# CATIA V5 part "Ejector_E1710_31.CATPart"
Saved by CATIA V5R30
Part number: Vyhazovac_7x160_7
Nomenclature: E1710/7x160
Description: MEUSBURGER
Property "Material": "1.221"
Publications: "__DrillHole", "Base"
Bounding box of the stored display mesh (mm): x -5.992 to 5.992, y -5.992 to 5.992, z 0 to 151
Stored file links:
  E:\Bakalarka\Model\Forma_v7\Ejector_E1710_31.CATPart
  E:\dev\MoldDesign\intel_a\startup\components\MoldCatalog\Ejector\Meusburger\Ejector_E1710\TableE1710.txt
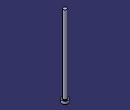
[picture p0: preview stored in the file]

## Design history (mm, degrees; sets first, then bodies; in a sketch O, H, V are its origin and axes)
Parameters
  Ref = "E1710/7x160" {design table}
  D1 = 7 mm {design table}
  D3 = 12 mm {design table}
  L = 160 mm {design table}
  L3 = 5 mm {design table}
  R = 0.5 mm {design table}
  k_d3 = 13 mm {design table}
  k_d1 = 7.2 mm {design table}
  k_F = 0.5 mm {design table}
  kl = 17 mm {design table}
  Mat = "1.221" {design table}
  HeatTreat = "ISO6751" {design table}
  Offset_Parting = 10 mm
  Anti_Rotation = "Normal"
  Anti_Rotation_D = 4 mm
  Anti_Rotation_D_Icut = 4 mm
  Add_Length_L = 1.3377 mm
  Add_Length_D3 = 0 mm
  SupplierRef = "Meusburger 2017"
  BmpRef = "F_MldEjectorD1"
  DrillHole_Length = 225 mm
  ValidationTest = false
  Anti_Rotation_D_min = 4 mm {= OffSet_D1 /2}
  Anti_Rotation_D_max = 5.925 mm {= D3/2-0.075mm}
  Anti_Rotation_D_ref = 4 mm {= Anti_Rotation_D}
  Anti_Rotation_D_Icut_ref = 4 mm {= Anti_Rotation_D_Icut}
  Anti_Rotation_Ref_Icut = 2.3246 mm
  Offset_L = 20 mm
  D = 7 mm {= D1}
  OffSet_D1 = 8 mm {= D1+2*R}
  OffSet_D3 = 13 mm {= D3+1mm}
  XG_Split = 54.5 mm
  YG_Split = -4 mm
  ZG_Split = -198 mm
  DirX_Split = 0 mm
  DirY_Split = 0 mm
  DirZ_Split = 1 mm
Set1 "BaseBody"
  Point1 "Base": (0, 0, 0)
  Plane1: type Offset, RefPlane xy-plane, Offset 225 {= DrillHole_Length}, reversed
  Sketch1 "Sketch.2" on xy-plane, origin (0, 0, 0), H (1, 0, 0), V (0, 1, 0)
    point P1 (-0.46, 1.1623)
    point P2 (0.46, 1.1623)
    construction line L1 (-0.46, 1.1623) -> (0.46, 1.1623)
    point P3 (0.46, -1.1623)
    line L2 (0.46, -1.1623) -> (0.46, 1.1623)
    point P4 (-0.46, -1.1623)
    construction line L3 (0.46, -1.1623) -> (-0.46, -1.1623)
    line L4 (-0.46, 1.1623) -> (-0.46, -1.1623)
    point P5 (-0.21, 1.1623)
    arc A1 centre (-0.21, 1.1623) radius 0.25 from (-0.21, 1.4123) to (-0.46, 1.1623) ccw
    point P7 (0.21, 1.1623)
    point P8 (0.21, 1.4123)
    arc A2 centre (0.21, 1.1623) radius 0.25 from (0.46, 1.1623) to (0.21, 1.4123) ccw
    line L5 (-0.21, 1.4123) -> (0.21, 1.4123)
    point P9 (-0.46, -1.1623)
    arc A3 centre (-0.21, -1.1623) radius 0.25 from (-0.46, -1.1623) to (-0.21, -1.4123) ccw
    point P11 (0.21, -1.4123)
    line L6 (-0.21, -1.4123) -> (0.21, -1.4123)
    point P12 (0.46, -1.1623)
    arc A4 centre (0.21, -1.1623) radius 0.25 from (0.21, -1.4123) to (0.46, -1.1623) ccw
    point P14 (-0.46, 1.1623)
    point P15 (-0.46, -1.1623)
    point P16 (0.46, 1.1623)
    point P17 (0.46, -1.1623)
    reference projected circle E1 centre (0, 0) radius 1.25 from edge [face of Shaft1 from Sketch2.L3 | face of Shaft1 from Sketch2.L4]
    reference projected circle E2 centre (0, 0) radius 1.25 from edge [face of Shaft1 from Sketch2.L3 | face of Shaft1 from Sketch2.L4]
    reference projected circle E3 centre (0, 0) radius 1.25 from edge [face of Shaft1 from Sketch2.L3 | face of Shaft1 from Sketch2.L4]
    reference projected circle E4 centre (0, 0) radius 1.25 from edge [face of Shaft1 from Sketch2.L3 | face of Shaft1 from Sketch2.L4]
    point P18 (-0.46, -1.1623)
    point P19 (-0.21, -1.4123)
    point P20 (0.21, -1.4123)
    point P21 (0.46, -1.1623)
    point P22 (-0.21, -1.4123)
    point P23 (0.21, -1.4123)
    distance P14 P15 = 2.3246 (reference)
    distance P16 P17 = 2.3246 (reference)
    distance L1 P14 = 0 (reference)
    radius A1 = 3.5
    distance L4 V = 4.01
    distance L2 V = 5.935
    distance L5 L6 = 12
    horizontal: L1 H, L3 H, L5 H
    vertical: L2 V, L4 V
    coincidence: P5 L1, P7 L1, P3 P12, P14 L4, P15 L4, P16 L2, P17 L2, P14 E1, P15 E2, P16 E3, P17 E4, P3 P21, P4 P18, P20 P23, P19 P22
    tangency: A1 L4, A2 L2, A2 L5, A1 L5
    symmetry: P1 P9 H, A1 A3 H, P8 P11 H, L5 L6 H, P2 P12 H, A2 A4 H
  DatumSurface1
Body1 "PartBody" (main body)
  Sketch2 "Sketch.1" on zx-plane, origin (0, 0, 0), H (-1, 0, 0), V (0, 0, 1)
    point P1 (0, 160)
    line L1 (3.5, 160) -> (0, 160)
    line L2 (3.5, 5) -> (3.5, 160)
    line L3 (6, 5) -> (3.5, 5)
    line L4 (6, 0) -> (6, 5)
    point P5 (0, 0)
    line L5 (0, 0) -> (6, 0)
    point P6 (0, 160)
    axis line L6 (0, 160) -> (0, 0)
    point P7 (0, 0)
    point P8 (3.5, 5)
    point P9 (3.5, 5)
    line L7 (0, 160) -> (0, 0)
    distance L5 L3 = 5 {= L3}
    distance L5 L1 = 160 {= L}
    distance L2 L6 = 3.5 {= D1 /2}
    distance L4 L6 = 6 {= D3 /2}
    coincidence: L6 P5, P1 L6, L5 H, L6 V, P7 O, P6 P1, P8 P9
    vertical: L2 V, L7 V
    horizontal: L1 H
  Shaft1 "Shaft.1": profile Sketch2, axis Sketch2.L6, angle 360
  Pocket1 "Pocket.1": profile Sketch1, direction (0, 0, 1), length 6, outer side, deactivated
  Pocket2 "Pocket.2": profile Sketch1, direction (0, 0, 1), length 6, outer side, deactivated
  Fillet1: radius 0.5 {= R}, on edge [face of Shaft1 from Sketch2.L2 | face of Shaft1 from Sketch2.L3]
  Pocket3: profile face of Shaft1 from Sketch2.L1, direction along face of Shaft1 from Sketch2.L1, length 225
  Pocket4: profile face of Pocket3, direction along face of Pocket3 reversed, up to face of DatumSurface1
Body2 "__DrillHole"
  Sketch3 "Sketch.3" on face of Shaft1, origin (0, 0, 0), H (1, 0, 0), V (0, -1, 0)
    point P1 (0, 0)
    reference projected point E1 (0, 0) from Point1
    coincidence: E1 P1
  Hole1 "Hole.1": placed by Sketch3, at (0, 0, 0) direction (0, 0, 1), diameter 8 {= OffSet_D1}, depth 140 {= L-Offset_L}
  Sketch4 "Sketch.4" on face of Shaft1, origin (0, 0, 0), H (1, 0, 0), V (0, -1, 0)
    point P1 (0, 0)
    reference projected point E1 (0, 0) from Point1
    coincidence: E1 P1
  Hole2 "Hole.2": placed by Sketch4, at (0, 0, 0) direction (0, 0, 1), diameter 7 {= D1}, depth 160 {= L}
  Sketch5 "Sketch.5" on face of Shaft1 from Sketch2.L3, origin (0, 0, 5), H (1, 0, 0), V (0, 1, 0)
    point P1 (0, 0)
    reference projected point E1 (0, 0) from Point1
    coincidence: E1 P1
  Hole3 "Hole.3": placed by Sketch5, at (0, 0, 5) direction (0, 0, -1), diameter 13 {= OffSet_D3}, depth 230 {= L3 +DrillHole_Length}
  Chamfer1: length 0.5 {= k_F}, angle 45, on edge [face of Hole1 | face of Hole3]
  Body3 "__Body.1"
    Pocket5 "Pocket.3": profile Sketch1, direction (0, 0, -1), length 225, opposite side length 5, deactivated
  Assemble1: tool Body3
  Chamfer2: length 0.5 {= k_F}, angle 45, on edge [start face of Pocket5 | face of Hole1], deactivated
  Body4 "__Body.2"
    Pocket6 "Pocket.4": profile Sketch1, direction (0, 0, -1), length 225, opposite side length 5, deactivated
  Assemble2: tool Body4
  Chamfer3: length 0.5 {= k_F}, angle 45, on edge [start face of Pocket6 | face of Hole1], deactivated
Relations
  design table "TableE1710", configuration 278, drives Ref, D1, D3, L, L3, R, k_d3, k_d1, k_F, kl, Mat, HeatTreat
  Offset_L = 20mm (deactivated)
  rule "Cut_Head_rule":
    let sketch_cut (length)
    let PartBody_Pocket_Sketch (Boolean)
    let I_PartBody_Pocket (Boolean)
    let D_PartBody_Pocket (Boolean)
    let N_DrillHole_Hole (Boolean)
    let N_DrillHole_Hole_Sketch (Boolean)
    let I_DrillHole_Pocket (Boolean)
    let D_DrillHole_Pocket (Boolean)
    /* --------------------------------------------------------------------------------------*/
    if Anti_Rotation =="Normal"
    {
    	sketch_cut=Anti_Rotation_D_max
    	PartBody_Pocket_Sketch = false
    	I_PartBody_Pocket = false
    	D_PartBody_Pocket = false
    	N_DrillHole_Hole = true
    	N_DrillHole_Hole_Sketch = true
    	I_DrillHole_Pocket = false
    	D_DrillHole_Pocket = false
    	Chamfer1.Activity= true
    	Chamfer2.Activity= false
    	Chamfer3.Activity= false
    }
    if Anti_Rotation == "I_Cut"
    {
    	sketch_cut=Anti_Rotation_D_Icut_ref
    	PartBody_Pocket_Sketch = true
    	I_PartBody_Pocket = true
    	D_PartBody_Pocket = false
    	N_DrillHole_Hole = false
    	N_DrillHole_Hole_Sketch = false
    	I_DrillHole_Pocket = true
    	D_DrillHole_Pocket = false
    	Chamfer1.Activity= false
    	Chamfer2.Activity= true
    	Chamfer3.Activity= false
    }
    if Anti_Rotation =="D_Cut"
    {
    	sketch_cut=Anti_Rotation_D_max
    	PartBody_Pocket_Sketch = true
    	I_PartBody_Pocket = false
    	D_PartBody_Pocket = true
    	N_DrillHole_Hole = false
    	N_DrillHole_Hole_Sketch = false
    	I_DrillHole_Pocket = false
    	D_DrillHole_Pocket = true
    	Chamfer1.Activity= false
    	Chamfer2.Activity= false
    	Chamfer3.Activity= true
    }
    /* --------------------------------------------------------------------------------------*/
    Sketch1.distance(L2 V) = sketch_cut+0.01mm
    Sketch1.distance(L4 V) =Anti_Rotation_D_ref+0.01mm
    Sketch1.radius(A1) =D/2
    Pocket5.FirstLimit.Depth = DrillHole_Length
    Pocket6.FirstLimit.Depth = DrillHole_Length
    Pocket1.FirstLimit.Depth = L3+1mm
    Pocket2.FirstLimit.Depth = L3+1mm
    Pocket5.SecondLimit.Depth = L3
    Pocket6.SecondLimit.Depth =L3
    Pocket1.Activity = I_PartBody_Pocket
    Pocket2.Activity = D_PartBody_Pocket
    Sketch1.Activity =PartBody_Pocket_Sketch
    Hole3.Activity= N_DrillHole_Hole
    Sketch5.Activity = N_DrillHole_Hole_Sketch
    Pocket5.Activity = I_DrillHole_Pocket
    Pocket6.Activity  = D_DrillHole_Pocket
  rule "Anti_Rotation_Icut_constrain":
    let Ref1(length)
    let Ref2(length)
    let Ref3(length)
    let Diam1(length)
    let Diam2(length)
    let Add_Length_Lmin (length)
    Ref1=Sketch1.distance(P14 P15)
    Ref2=Sketch1.distance(P16 P17)
    Diam1=D
    Diam2=D3
    /* --------------------------------------------------------------------*/
    if Ref1 >Ref2
    	Anti_Rotation_Ref_Icut = Ref1
    else
    	Anti_Rotation_Ref_Icut  =Ref2
    Add_Length_D3 .InferiorRange=Anti_Rotation_Ref_Icut /2+Diam1/2 -Diam2/2
    if Add_Length_D3 .InferiorRange<0mm
    	Add_Length_D3 .InferiorRange=0mm
    if ValidationTest == "true"
    	Ref3   = 2*Add_Length_L +Anti_Rotation_Ref_Icut  +2*Diam1/2
    else
    	Ref3  =Diam2+2*Add_Length_D3
    if Ref3 <Diam2
    {
    	Ref3 =Diam2
    }
    /* --------------------------------------------------------------------*/
    Sketch1.distance(L5 L6) = Ref3
    Add_Length_L .InferiorRange=Diam2/2-Anti_Rotation_Ref_Icut/2-Diam1/2
    Add_Length_Lmin=Diam2/2-Anti_Rotation_Ref_Icut/2-Diam1/2
    if Add_Length_Lmin<0mm
    	Add_Length_L .InferiorRange=0mm
    else
    	Add_Length_L .InferiorRange=Add_Length_Lmin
